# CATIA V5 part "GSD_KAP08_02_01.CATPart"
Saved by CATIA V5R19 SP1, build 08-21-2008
Part number: GSD_ANALYSIS_01
Description: Beispielmodell für Verbindungsüberprüfungsanalyse / Kurvenanalyse.  Copyright (c) 2009 Maik Hertha IT Consultants
Bounding box of the stored display mesh (mm): x -42.091 to 209.868, y 0 to 168.379, z 0 to 0
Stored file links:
  \GSD_BUCH_UEBUNG\GSD_KAP08_02_01.CATPart
  C:\Program Files\Dassault Systemes\B19\win_b64\startup\materials\Catalog.CATMaterial
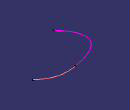
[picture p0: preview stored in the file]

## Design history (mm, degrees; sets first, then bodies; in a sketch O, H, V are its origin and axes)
AxisSystem1 "Absolute Axis System": origin (0, 0, 0), X (1, 0, 0), Y (0, 1, 0), Z (0, 0, 1)
Set1
  St3DCurveFeature1 "CATSt3DCurveFeatureName": Order 6, CreationType 2, ClosureMode false, ConstructionPoints ({point type Coord, X 0, Y 0, Z 0}; {point type Coord, X -41.4009, Y 92.3273, Z 0}; {point type Coord, X 79.6071, Y 164.7638, Z 0}), SymmetryMode false
  St3DCurveFeature2 "CATSt3DCurveFeatureName": Order 6, CreationType 2, ClosureMode false, ConstructionPoints ({point type Coord, X 79.9666, Y 164.8322, Z 0}; {point type Coord, X 137.8508, Y 165.99, Z 0}; {point type Coord, X 209.8685, Y 127.6922, Z 0}), SymmetryMode false
  St3DCurveFeature3 "CATSt3DCurveFeatureName": Order 6, CreationType 2, ClosureMode false, ConstructionPoints ({point type Coord, X 207.4679, Y 132.9447, Z 0}; {point type Coord, X 158.7347, Y 190.671, Z 0}; {point type Coord, X 79.8143, Y 233.4626, Z 0}), SymmetryMode false
Body1 (main body)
